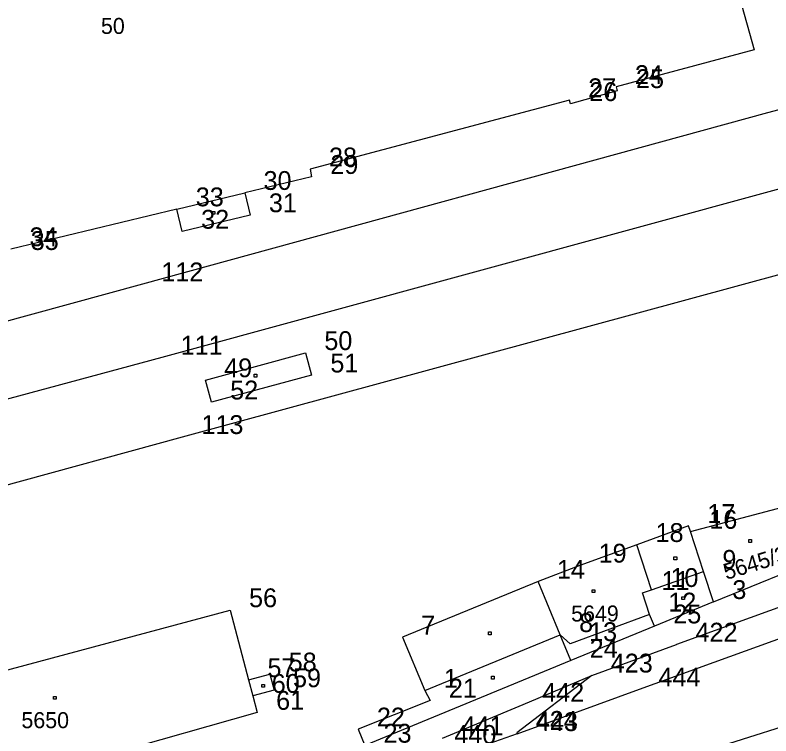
# Model space of a CAD drawing. Extents: x -822293 to -820259, y -1071573 to -1068794.
# Drawn here: x -821738.1 to -821657.8, y -1070350.9 to -1070274.3 of the extents above; entities that cross this region are included whole.
import ezdxf

# ---------------------------------------------------------------- set-up
doc = ezdxf.new("R2010")
doc.units = 0
for name, color, linetype in [('Vrstva 11', 7, 'Continuous'), ('Vrstva 16', 7, 'Continuous'), ('Vrstva 2', 7, 'Continuous'), ('Vrstva 3', 7, 'Continuous'), ('Vrstva 6', 7, 'Continuous'), ('Vrstva 8', 7, 'Continuous'), ('Vrstva 9', 7, 'Continuous')]:
    doc.layers.add(name, color=color, linetype=linetype)

# ---------------------------------------------------------------- blocks, each defined once
blk = doc.blocks.new('Z402')
at = {"layer": 'Vrstva 2'}
for p, q in [((-10, 10), (20, 10)), ((-10, -20), (-10, 10)), ((20, 10), (20, -20)), ((20, -20), (-10, -20))]:
    blk.add_line(p, q, dxfattribs=at)

msp = doc.modelspace()

# ---------------------------------------------------------------- linework, layer by layer
at = {"layer": 'Vrstva 2'}
for p, q in [((-821720.29, -1070319.13), (-821654.62, -1070301.25)), ((-821746.56, -1070326.32), (-821720.29, -1070319.13)), ((-821666.33, -1070329.2), (-821654.87, -1070326.15)), ((-821666.54, -1070328.58), (-821672.04, -1070330.6)), ((-821666.33, -1070329.2), (-821666.54, -1070328.58)), ((-821664.94, -1070333.45), (-821666.33, -1070329.2)), ((-821672.04, -1070330.6), (-821678.09, -1070332.79)), ((-821663.88, -1070336.66), (-821653.3, -1070332.33)), ((-821678.09, -1070332.79), (-821682.52, -1070334.51)), ((-821663.88, -1070336.66), (-821664.94, -1070333.45)), ((-821682.52, -1070334.51), (-821696.94, -1070340.43)), ((-821663.88, -1070336.66), (-821670.16, -1070339.25)), ((-821748.92, -1070346.58), (-821715.23, -1070337.53)), ((-821715.23, -1070337.53), (-821713.27, -1070344.96)), ((-821670.16, -1070339.25), (-821679.04, -1070342.9)), ((-821696.94, -1070340.43), (-821694.54, -1070346.09)), ((-821679.04, -1070342.9), (-821700.94, -1070351.92)), ((-821713.27, -1070344.96), (-821711.02, -1070344.36)), ((-821711.02, -1070344.36), (-821710.56, -1070346.03)), ((-821710.56, -1070346.03), (-821712.82, -1070346.63)), ((-821694.54, -1070346.09), (-821694, -1070347.13)), ((-821712.82, -1070346.63), (-821712.35, -1070348.43)), ((-821694, -1070347.13), (-821701.65, -1070350.2)), ((-821712.35, -1070348.43), (-821745.89, -1070357.86)), ((-821701.65, -1070350.2), (-821700.94, -1070351.92))]:
    msp.add_line(p, q, dxfattribs=at)
at = {"layer": 'Vrstva 3'}
for p, q in [((-821558.07, -1070257.3), (-821658.14, -1070284.72)), ((-821661.45, -1070271.25), (-821659.57, -1070278.02)), ((-821659.57, -1070278.02), (-821674.24, -1070281.95)), ((-821674.24, -1070281.95), (-821674.12, -1070282.38)), ((-821674.12, -1070282.38), (-821679.08, -1070283.76)), ((-821679.2, -1070283.35), (-821706.74, -1070290.7)), ((-821679.08, -1070283.76), (-821679.2, -1070283.35)), ((-821658.14, -1070284.72), (-821724.55, -1070302.91)), ((-821706.74, -1070290.7), (-821706.59, -1070291.5)), ((-821706.59, -1070291.5), (-821713.69, -1070293.2)), ((-821656.44, -1070292.68), (-821722.5, -1070310.7)), ((-821720.89, -1070294.94), (-821713.69, -1070293.2)), ((-821713.69, -1070293.2), (-821713.12, -1070295.57)), ((-821720.89, -1070294.94), (-821738.55, -1070299.18)), ((-821720.32, -1070297.32), (-821720.89, -1070294.94)), ((-821713.12, -1070295.57), (-821720.32, -1070297.32)), ((-821724.55, -1070302.91), (-821765.81, -1070314.15)), ((-821722.5, -1070310.7), (-821748.88, -1070317.82)), ((-821717.87, -1070313.1), (-821707.23, -1070310.21)), ((-821707.23, -1070310.21), (-821706.59, -1070312.59)), ((-821717.23, -1070315.46), (-821717.87, -1070313.1)), ((-821706.59, -1070312.59), (-821717.23, -1070315.46)), ((-821670.46, -1070335.38), (-821672.04, -1070330.6)), ((-821670.46, -1070335.38), (-821664.94, -1070333.45)), ((-821680.16, -1070340.17), (-821682.52, -1070334.51)), ((-821671.41, -1070335.7), (-821670.46, -1070335.38)), ((-821670.68, -1070337.99), (-821671.41, -1070335.7)), ((-821653.31, -1070335.92), (-821667.8, -1070341.18)), ((-821670.68, -1070337.99), (-821679.1, -1070341.13)), ((-821670.16, -1070339.25), (-821670.68, -1070337.99)), ((-821671.73, -1070345.95), (-821650.82, -1070338.35)), ((-821694.54, -1070346.09), (-821680.16, -1070340.17)), ((-821679.04, -1070342.9), (-821680.16, -1070340.17)), ((-821679.1, -1070341.13), (-821680.16, -1070340.17)), ((-821676.8, -1070344.47), (-821667.8, -1070341.18)), ((-821676.8, -1070344.47), (-821684.78, -1070350.56)), ((-821684.09, -1070347.58), (-821676.8, -1070344.47)), ((-821713.27, -1070344.96), (-821712.82, -1070346.63)), ((-821684.75, -1070350.69), (-821671.73, -1070345.95)), ((-821692.66, -1070351.13), (-821684.09, -1070347.58)), ((-821678.84, -1070356.92), (-821653.29, -1070348.88)), ((-821684.75, -1070350.69), (-821693.1, -1070353.61)), ((-821684.78, -1070350.56), (-821684.75, -1070350.69))]:
    msp.add_line(p, q, dxfattribs=at)
at = {"layer": 'Vrstva 8'}
for p, q in [((-821659.57, -1070278.02), (-821659.57, -1070278.02)), ((-821674.24, -1070281.95), (-821674.24, -1070281.95)), ((-821674.12, -1070282.38), (-821674.12, -1070282.38)), ((-821679.2, -1070283.35), (-821679.2, -1070283.35)), ((-821679.08, -1070283.76), (-821679.08, -1070283.76)), ((-821658.14, -1070284.72), (-821658.14, -1070284.72)), ((-821706.74, -1070290.7), (-821706.74, -1070290.7)), ((-821706.59, -1070291.5), (-821706.59, -1070291.5)), ((-821713.69, -1070293.2), (-821713.69, -1070293.2)), ((-821720.89, -1070294.94), (-821720.89, -1070294.94)), ((-821713.12, -1070295.57), (-821713.12, -1070295.57)), ((-821720.32, -1070297.32), (-821720.32, -1070297.32)), ((-821724.55, -1070302.91), (-821724.55, -1070302.91)), ((-821722.5, -1070310.7), (-821722.5, -1070310.7)), ((-821707.23, -1070310.21), (-821707.23, -1070310.21)), ((-821717.87, -1070313.1), (-821717.87, -1070313.1)), ((-821706.59, -1070312.59), (-821706.59, -1070312.59)), ((-821717.23, -1070315.46), (-821717.23, -1070315.46)), ((-821720.29, -1070319.13), (-821720.29, -1070319.13)), ((-821666.54, -1070328.58), (-821666.54, -1070328.58)), ((-821666.33, -1070329.2), (-821666.33, -1070329.2)), ((-821672.04, -1070330.6), (-821672.04, -1070330.6)), ((-821678.09, -1070332.79), (-821678.09, -1070332.79)), ((-821664.94, -1070333.45), (-821664.94, -1070333.45)), ((-821682.52, -1070334.51), (-821682.52, -1070334.51)), ((-821671.41, -1070335.7), (-821671.41, -1070335.7)), ((-821670.46, -1070335.38), (-821670.46, -1070335.38)), ((-821663.88, -1070336.66), (-821663.88, -1070336.66)), ((-821715.23, -1070337.53), (-821715.23, -1070337.53)), ((-821670.68, -1070337.99), (-821670.68, -1070337.99)), ((-821670.16, -1070339.25), (-821670.16, -1070339.25)), ((-821696.94, -1070340.43), (-821696.94, -1070340.43)), ((-821680.16, -1070340.17), (-821680.16, -1070340.17)), ((-821679.1, -1070341.13), (-821679.1, -1070341.13)), ((-821667.8, -1070341.18), (-821667.8, -1070341.18)), ((-821679.04, -1070342.9), (-821679.04, -1070342.9)), ((-821711.02, -1070344.36), (-821711.02, -1070344.36)), ((-821676.8, -1070344.47), (-821676.8, -1070344.47)), ((-821713.27, -1070344.96), (-821713.27, -1070344.96)), ((-821710.56, -1070346.03), (-821710.56, -1070346.03)), ((-821694.54, -1070346.09), (-821694.54, -1070346.09)), ((-821671.73, -1070345.95), (-821671.73, -1070345.95)), ((-821712.82, -1070346.63), (-821712.82, -1070346.63)), ((-821694, -1070347.13), (-821694, -1070347.13)), ((-821684.09, -1070347.58), (-821684.09, -1070347.58)), ((-821712.35, -1070348.43), (-821712.35, -1070348.43)), ((-821701.65, -1070350.2), (-821701.65, -1070350.2)), ((-821684.78, -1070350.56), (-821684.78, -1070350.56)), ((-821684.75, -1070350.69), (-821684.75, -1070350.69))]:
    msp.add_line(p, q, dxfattribs=at)

# ---------------------------------------------------------------- block references
at = {"layer": 'Vrstva 11', "xscale": 0.01, "yscale": 0.01}
for p in [(-821717.07, -1070295.28), (-821712.6, -1070312.59), (-821660.03, -1070330.14), (-821667.99, -1070331.99), (-821676.68, -1070335.47), (-821667.16, -1070336.22), (-821687.7, -1070339.95), (-821687.37, -1070344.67), (-821711.77, -1070345.53), (-821733.92, -1070346.8)]:
    msp.add_blockref('Z402', p, dxfattribs=at)

# ---------------------------------------------------------------- texts
at = {"layer": 'Vrstva 16'}
msp.add_text('50', height=1.7, dxfattribs=at).set_placement((-821728.963, -1070276.33))
at = {"layer": 'Vrstva 6'}
msp.add_text('5645/3', height=1.7, rotation=17, dxfattribs=at).set_placement((-821662.53, -1070334.34))
for s, p in [('5649', (-821679.01, -1070338.75)), ('5650', (-821737.413, -1070350.08))]:
    msp.add_text(s, height=1.7, dxfattribs=at).set_placement(p)
at = {"layer": 'Vrstva 9'}
for s, p in [('24', (-821672.24, -1070281.65)), ('25', (-821672.12, -1070282.08)), ('27', (-821677.2, -1070283.05)), ('26', (-821677.08, -1070283.46)), ('28', (-821704.74, -1070290.4)), ('29', (-821704.59, -1070291.2)), ('30', (-821711.69, -1070292.9)), ('33', (-821718.89, -1070294.64)), ('31', (-821711.12, -1070295.27)), ('32', (-821718.32, -1070297.02)), ('34', (-821736.55, -1070298.88)), ('35', (-821736.43, -1070299.28)), ('112', (-821722.55, -1070302.61)), ('111', (-821720.5, -1070310.4)), ('50', (-821705.23, -1070309.91)), ('49', (-821715.87, -1070312.8)), ('51', (-821704.59, -1070312.29)), ('52', (-821715.23, -1070315.16)), ('113', (-821718.29, -1070318.83)), ('17', (-821664.54, -1070328.28)), ('16', (-821664.33, -1070328.9)), ('18', (-821670.04, -1070330.3)), ('19', (-821676.09, -1070332.49)), ('9', (-821662.94, -1070333.15)), ('14', (-821680.52, -1070334.21)), ('11', (-821669.41, -1070335.4)), ('10', (-821668.46, -1070335.08)), ('3', (-821661.88, -1070336.36)), ('56', (-821713.23, -1070337.23)), ('12', (-821668.68, -1070337.69)), ('25', (-821668.16, -1070338.95)), ('7', (-821694.94, -1070340.13)), ('8', (-821678.16, -1070339.87)), ('13', (-821677.1, -1070340.83)), ('422', (-821665.8, -1070340.88)), ('24', (-821677.04, -1070342.6)), ('58', (-821709.02, -1070344.06)), ('423', (-821674.8, -1070344.17)), ('57', (-821711.27, -1070344.66)), ('59', (-821708.56, -1070345.73)), ('1', (-821692.54, -1070345.79)), ('444', (-821669.73, -1070345.65)), ('60', (-821710.82, -1070346.33)), ('21', (-821692, -1070346.83)), ('442', (-821682.09, -1070347.28)), ('61', (-821710.35, -1070348.13)), ('22', (-821699.65, -1070349.9)), ('424', (-821682.78, -1070350.26)), ('443', (-821682.75, -1070350.39)), ('441', (-821690.66, -1070350.83)), ('23', (-821698.94, -1070351.62)), ('440', (-821691.42, -1070351.75))]:
    msp.add_text(s, height=2, dxfattribs=at).set_placement(p)

doc.saveas('drawing.dxf')
